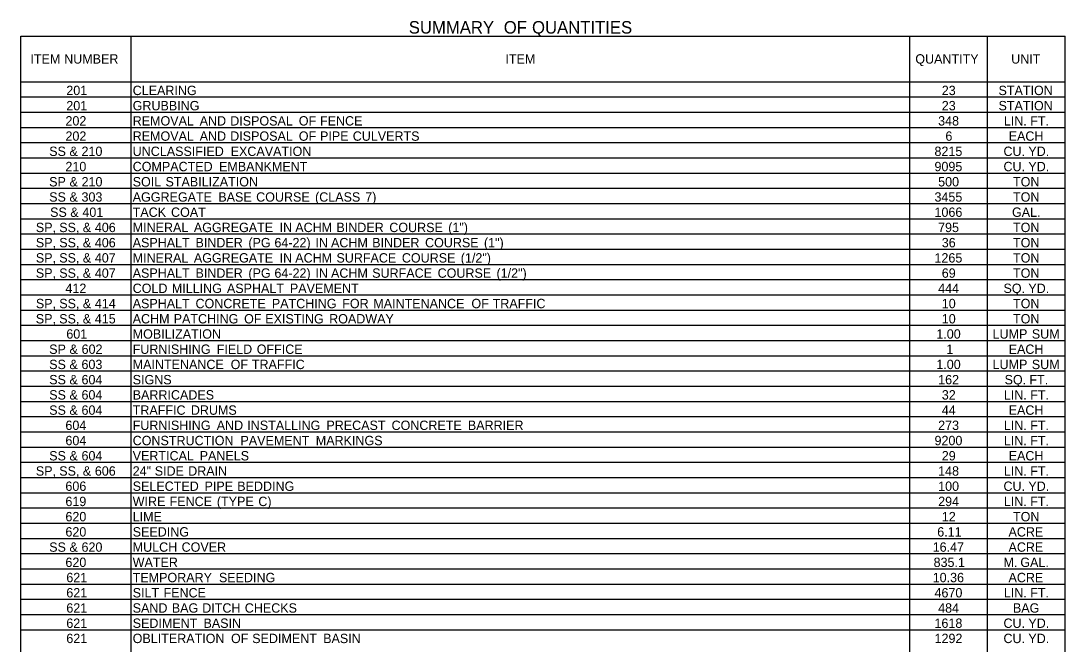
# Model space of a CAD drawing. Extents: x 1940653 to 1945779, y 534266 to 535271.
# Drawn here: x 1944649 to 1945251, y 534817 to 535176 of the extents above; entities that cross this region are included whole.
import ezdxf

# ---------------------------------------------------------------- set-up
doc = ezdxf.new("R2010")
doc.units = 0
doc.layers.add('Default', color=7, linetype='Continuous')

msp = doc.modelspace()

# ---------------------------------------------------------------- linework, layer by layer
at = {"layer": 'Default'}
for p, q in [((1944648.86, 535167.56), (1944712.48, 535167.56)), ((1944648.86, 535167.56), (1945251.26, 535167.56)), ((1944648.86, 534632.28), (1944648.86, 535167.56)), ((1944648.86, 534632.28), (1944648.86, 535167.56)), ((1944712.48, 534684.93), (1944712.48, 535167.56)), ((1945161.76, 534632.28), (1945161.76, 535167.56)), ((1945206.51, 534632.28), (1945206.51, 535167.56)), ((1945206.51, 534684.93), (1945206.51, 535167.56)), ((1945251.26, 534632.28), (1945251.26, 535167.56)), ((1944648.86, 535141.23), (1945251.26, 535141.23)), ((1944712.48, 534684.93), (1944712.48, 535141.23)), ((1945161.76, 534684.93), (1945161.76, 535141.23)), ((1944648.86, 535132.46), (1945251.26, 535132.46)), ((1944648.86, 535123.68), (1945251.26, 535123.68)), ((1944648.86, 535114.91), (1945251.26, 535114.91)), ((1944648.86, 535106.13), (1945251.26, 535106.13)), ((1944648.86, 535097.36), (1945251.26, 535097.36)), ((1944648.86, 535088.58), (1945251.26, 535088.58)), ((1944648.86, 535079.81), (1945251.26, 535079.81)), ((1944648.86, 535071.03), (1945251.26, 535071.03)), ((1944648.86, 535062.26), (1945251.26, 535062.26)), ((1944648.86, 535053.48), (1945251.26, 535053.48)), ((1944648.86, 535044.71), (1945251.26, 535044.71)), ((1944648.86, 535035.93), (1945251.26, 535035.93)), ((1944648.86, 535027.16), (1945251.26, 535027.16)), ((1944648.86, 535018.38), (1945251.26, 535018.38)), ((1944648.86, 535009.61), (1945251.26, 535009.61)), ((1944648.86, 535000.83), (1945251.26, 535000.83)), ((1944648.86, 534992.06), (1945251.26, 534992.06)), ((1944648.86, 534983.28), (1945251.26, 534983.28)), ((1944648.86, 534974.51), (1945251.26, 534974.51)), ((1944648.86, 534965.73), (1945251.26, 534965.73)), ((1944648.86, 534956.96), (1945251.26, 534956.96)), ((1944648.86, 534948.18), (1945251.26, 534948.18)), ((1944648.86, 534939.41), (1945251.26, 534939.41)), ((1944648.86, 534930.63), (1945251.26, 534930.63)), ((1944648.86, 534921.86), (1945251.26, 534921.86)), ((1944648.86, 534913.08), (1945251.26, 534913.08)), ((1944648.86, 534904.31), (1945251.26, 534904.31)), ((1944648.86, 534895.53), (1945251.26, 534895.53)), ((1944648.86, 534886.76), (1945251.26, 534886.76)), ((1944648.86, 534877.98), (1945251.26, 534877.98)), ((1944648.86, 534869.21), (1945251.26, 534869.21)), ((1944648.86, 534860.43), (1945251.26, 534860.43)), ((1944648.86, 534851.66), (1945251.26, 534851.66)), ((1944648.86, 534842.88), (1945251.26, 534842.88)), ((1944648.86, 534834.11), (1945251.26, 534834.11)), ((1944648.86, 534825.33), (1945251.26, 534825.33))]:
    msp.add_line(p, q, dxfattribs=at)

# ---------------------------------------------------------------- texts
for s, height, p in [(' SUMMARY', 7.2, (1944869.96, 535169)), (' OF', 7.2, (1944924.75, 535169)), (' QUANTITIES', 7.2, (1944941.05, 535169)), ('ITEM', 5.4, (1944654.34, 535151.7)), (' NUMBER', 5.4, (1944671.82, 535151.7)), ('ITEM', 5.4, (1944928.38, 535151.7)), ('QUANTITY', 5.4, (1945164.85, 535151.7)), ('UNIT', 5.4, (1945220.16, 535151.7)), ('201', 5.4, (1944675.07, 535133.54)), ('CLEARING', 5.4, (1944713.36, 535133.54)), ('23', 5.4, (1945180.11, 535133.54)), ('STATION', 5.4, (1945212.85, 535133.54)), ('201', 5.4, (1944675.07, 535124.76)), ('GRUBBING', 5.4, (1944713.36, 535124.76)), ('23', 5.4, (1945180.11, 535124.76)), ('STATION', 5.4, (1945212.85, 535124.76)), ('202', 5.4, (1944674.58, 535115.99)), ('REMOVAL', 5.4, (1944713.36, 535115.99)), (' AND', 5.4, (1944749.99, 535115.99)), (' DISPOSAL', 5.4, (1944767.61, 535115.99)), (' OF', 5.4, (1944807.18, 535115.99)), (' FENCE', 5.4, (1944819.41, 535115.99)), ('348', 5.4, (1945178.01, 535115.99)), ('LIN.', 5.4, (1945215.92, 535115.99)), (' FT.', 5.4, (1945229.1, 535115.99)), ('202', 5.4, (1944674.58, 535107.21)), ('REMOVAL', 5.4, (1944713.36, 535107.21)), (' AND', 5.4, (1944749.99, 535107.21)), (' DISPOSAL', 5.4, (1944767.61, 535107.21)), (' OF', 5.4, (1944807.18, 535107.21)), (' PIPE', 5.4, (1944819.41, 535107.21)), (' CULVERTS', 5.4, (1944838.3, 535107.21)), ('6', 5.4, (1945182.21, 535107.21)), ('EACH', 5.4, (1945218.71, 535107.21)), ('SS', 5.4, (1944665.2, 535098.44)), (' &', 5.4, (1944674.87, 535098.44)), (' 210', 5.4, (1944681.83, 535098.44)), ('UNCLASSIFIED', 5.4, (1944713.36, 535098.44)), (' EXCAVATION', 5.4, (1944767.88, 535098.44)), ('8215', 5.4, (1945175.9, 535098.44)), ('CU.', 5.4, (1945215.71, 535098.44)), (' YD.', 5.4, (1945228.05, 535098.44)), ('210', 5.4, (1944674.56, 535089.66)), ('COMPACTED', 5.4, (1944713.36, 535089.66)), (' EMBANKMENT', 5.4, (1944761.17, 535089.66)), ('9095', 5.4, (1945175.9, 535089.66)), ('CU.', 5.4, (1945215.71, 535089.66)), (' YD.', 5.4, (1945228.05, 535089.66)), ('SP', 5.4, (1944665.17, 535080.89)), (' &', 5.4, (1944674.9, 535080.89)), (' 210', 5.4, (1944681.86, 535080.89)), ('SOIL', 5.4, (1944713.36, 535080.89)), (' STABILIZATION', 5.4, (1944730.28, 535080.89)), ('500', 5.4, (1945178.03, 535080.89)), ('TON', 5.4, (1945221.23, 535080.89)), ('SS', 5.4, (1944665.19, 535072.11)), (' &', 5.4, (1944674.86, 535072.11)), (' 303', 5.4, (1944681.82, 535072.11)), ('AGGREGATE', 5.4, (1944713.36, 535072.11)), (' BASE', 5.4, (1944760.75, 535072.11)), (' COURSE', 5.4, (1944782.58, 535072.11)), (' (CLASS', 5.4, (1944816.56, 535072.11)), (' 7)', 5.4, (1944845.51, 535072.11)), ('3455', 5.4, (1945175.9, 535072.11)), ('TON', 5.4, (1945221.23, 535072.11)), ('SS', 5.4, (1944665.71, 535063.34)), (' &', 5.4, (1944675.38, 535063.34)), (' 401', 5.4, (1944682.34, 535063.34)), ('TACK', 5.4, (1944713.36, 535063.34)), (' COAT', 5.4, (1944733.47, 535063.34)), ('1066', 5.4, (1945175.92, 535063.34)), ('GAL.', 5.4, (1945220.62, 535063.34)), ('SP,', 5.4, (1944657.49, 535054.56)), (' SS,', 5.4, (1944668.98, 535054.56)), (' &', 5.4, (1944682.56, 535054.56)), (' 406', 5.4, (1944689.52, 535054.56)), ('MINERAL', 5.4, (1944713.36, 535054.56)), (' AGGREGATE', 5.4, (1944746.63, 535054.56)), (' IN', 5.4, (1944796.12, 535054.56)), (' ACHM', 5.4, (1944805.14, 535054.56)), (' BINDER', 5.4, (1944828.89, 535054.56)), (' COURSE', 5.4, (1944859.39, 535054.56)), (' (1")', 5.4, (1944893.37, 535054.56)), ('795', 5.4, (1945177.99, 535054.56)), ('TON', 5.4, (1945221.23, 535054.56)), ('SP,', 5.4, (1944657.49, 535045.79)), (' SS,', 5.4, (1944668.98, 535045.79)), (' &', 5.4, (1944682.56, 535045.79)), (' 406', 5.4, (1944689.52, 535045.79)), ('ASPHALT', 5.4, (1944713.36, 535045.79)), (' BINDER', 5.4, (1944747.59, 535045.79)), (' (PG', 5.4, (1944778.09, 535045.79)), (' 64-22)', 5.4, (1944793.13, 535045.79)), (' IN', 5.4, (1944816.75, 535045.79)), (' ACHM', 5.4, (1944825.77, 535045.79)), (' BINDER', 5.4, (1944849.52, 535045.79)), (' COURSE', 5.4, (1944880.02, 535045.79)), (' (1")', 5.4, (1944914, 535045.79)), ('36', 5.4, (1945180.11, 535045.79)), ('TON', 5.4, (1945221.23, 535045.79)), ('SP,', 5.4, (1944657.49, 535037.01)), (' SS,', 5.4, (1944668.98, 535037.01)), (' &', 5.4, (1944682.56, 535037.01)), (' 407', 5.4, (1944689.52, 535037.01)), ('MINERAL', 5.4, (1944713.36, 535037.01)), (' AGGREGATE', 5.4, (1944746.63, 535037.01)), (' IN', 5.4, (1944796.12, 535037.01)), (' ACHM', 5.4, (1944805.14, 535037.01)), (' SURFACE', 5.4, (1944828.89, 535037.01)), (' COURSE', 5.4, (1944866.64, 535037.01)), (' (1/2")', 5.4, (1944900.62, 535037.01)), ('1265', 5.4, (1945175.9, 535037.01)), ('TON', 5.4, (1945221.23, 535037.01)), ('SP,', 5.4, (1944657.49, 535028.24)), (' SS,', 5.4, (1944668.98, 535028.24)), (' &', 5.4, (1944682.56, 535028.24)), (' 407', 5.4, (1944689.52, 535028.24)), ('ASPHALT', 5.4, (1944713.36, 535028.24)), (' BINDER', 5.4, (1944747.59, 535028.24)), (' (PG', 5.4, (1944778.09, 535028.24)), (' 64-22)', 5.4, (1944793.13, 535028.24)), (' IN', 5.4, (1944816.75, 535028.24)), (' ACHM', 5.4, (1944825.77, 535028.24)), (' SURFACE', 5.4, (1944849.52, 535028.24)), (' COURSE', 5.4, (1944887.27, 535028.24)), (' (1/2")', 5.4, (1944921.24, 535028.24)), ('69', 5.4, (1945180.11, 535028.24)), ('TON', 5.4, (1945221.23, 535028.24)), ('412', 5.4, (1944674.58, 535019.46)), ('COLD', 5.4, (1944713.36, 535019.46)), (' MILLING', 5.4, (1944733.92, 535019.46)), (' ASPHALT', 5.4, (1944765.72, 535019.46)), ('SQ.', 5.4, (1945215.71, 535019.46)), (' PAVEMENT', 5.4, (1944802.05, 535019.46)), ('444', 5.4, (1945178.03, 535019.46)), (' YD.', 5.4, (1945228.05, 535019.46)), ('SP,', 5.4, (1944657.5, 535010.69)), (' SS,', 5.4, (1944668.99, 535010.69)), (' &', 5.4, (1944682.58, 535010.69)), (' 414', 5.4, (1944689.53, 535010.69)), ('ASPHALT', 5.4, (1944713.36, 535010.69)), (' CONCRETE', 5.4, (1944747.59, 535010.69)), (' PATCHING', 5.4, (1944791.63, 535010.69)), (' FOR', 5.4, (1944832.24, 535010.69)), (' MAINTENANCE', 5.4, (1944850.16, 535010.69)), (' OF', 5.4, (1944906.77, 535010.69)), (' TRAFFIC', 5.4, (1944919, 535010.69)), ('10', 5.4, (1945180.12, 535010.69)), ('TON', 5.4, (1945221.23, 535010.69)), ('SP,', 5.4, (1944657.46, 535001.91)), (' SS,', 5.4, (1944668.96, 535001.91)), (' &', 5.4, (1944682.54, 535001.91)), (' 415', 5.4, (1944689.5, 535001.91)), ('ACHM', 5.4, (1944713.36, 535001.91)), (' PATCHING', 5.4, (1944735.01, 535001.91)), (' OF', 5.4, (1944775.62, 535001.91)), (' EXISTING', 5.4, (1944787.85, 535001.91)), (' ROADWAY', 5.4, (1944824.69, 535001.91)), ('10', 5.4, (1945180.12, 535001.91)), ('TON', 5.4, (1945221.23, 535001.91)), ('601', 5.4, (1944675.07, 534993.14)), ('MOBILIZATION', 5.4, (1944713.36, 534993.14)), ('1.00', 5.4, (1945176.98, 534993.14)), ('LUMP', 5.4, (1945209.42, 534993.14)), (' SUM', 5.4, (1945230.06, 534993.14)), ('SP', 5.4, (1944665.18, 534984.36)), (' &', 5.4, (1944674.92, 534984.36)), (' 602', 5.4, (1944681.88, 534984.36)), ('FURNISHING', 5.4, (1944713.36, 534984.36)), (' FIELD', 5.4, (1944759.83, 534984.36)), (' OFFICE', 5.4, (1944782.91, 534984.36)), ('1', 5.4, (1945182.73, 534984.36)), ('EACH', 5.4, (1945218.71, 534984.36)), ('SS', 5.4, (1944665.19, 534975.59)), (' &', 5.4, (1944674.86, 534975.59)), (' 603', 5.4, (1944681.82, 534975.59)), ('MAINTENANCE', 5.4, (1944713.36, 534975.59)), (' OF', 5.4, (1944767.88, 534975.59)), (' TRAFFIC', 5.4, (1944780.1, 534975.59)), ('1.00', 5.4, (1945176.98, 534975.59)), ('LUMP', 5.4, (1945209.42, 534975.59)), (' SUM', 5.4, (1945230.06, 534975.59)), ('SS', 5.4, (1944665.2, 534966.81)), (' &', 5.4, (1944674.87, 534966.81)), (' 604', 5.4, (1944681.83, 534966.81)), ('SIGNS', 5.4, (1944713.36, 534966.81)), ('162', 5.4, (1945178.04, 534966.81)), ('SQ.', 5.4, (1945216.34, 534966.81)), (' FT.', 5.4, (1945228.68, 534966.81)), ('SS', 5.4, (1944665.2, 534958.04)), (' &', 5.4, (1944674.87, 534958.04)), (' 604', 5.4, (1944681.83, 534958.04)), ('BARRICADES', 5.4, (1944713.36, 534958.04)), ('32', 5.4, (1945180.14, 534958.04)), ('LIN.', 5.4, (1945215.92, 534958.04)), (' FT.', 5.4, (1945229.1, 534958.04)), ('SS', 5.4, (1944665.2, 534949.26)), (' &', 5.4, (1944674.87, 534949.26)), (' 604', 5.4, (1944681.83, 534949.26)), ('TRAFFIC', 5.4, (1944713.36, 534949.26)), (' DRUMS', 5.4, (1944744.91, 534949.26)), ('44', 5.4, (1945180.12, 534949.26)), ('EACH', 5.4, (1945218.71, 534949.26)), ('604', 5.4, (1944674.56, 534940.49)), ('FURNISHING', 5.4, (1944713.36, 534940.49)), (' AND', 5.4, (1944759.83, 534940.49)), (' INSTALLING', 5.4, (1944777.46, 534940.49)), (' PRECAST', 5.4, (1944823.1, 534940.49)), (' CONCRETE', 5.4, (1944860.69, 534940.49)), (' BARRIER', 5.4, (1944904.72, 534940.49)), ('273', 5.4, (1945178.02, 534940.49)), ('LIN.', 5.4, (1945215.92, 534940.49)), (' FT.', 5.4, (1945229.1, 534940.49)), ('604', 5.4, (1944674.56, 534931.71)), ('CONSTRUCTION', 5.4, (1944713.36, 534931.71)), (' PAVEMENT', 5.4, (1944773.52, 534931.71)), (' MARKINGS', 5.4, (1944816.98, 534931.71)), ('9200', 5.4, (1945175.93, 534931.71)), ('LIN.', 5.4, (1945215.92, 534931.71)), (' FT.', 5.4, (1945229.1, 534931.71)), ('SS', 5.4, (1944665.2, 534922.94)), (' &', 5.4, (1944674.87, 534922.94)), (' 604', 5.4, (1944681.83, 534922.94)), ('VERTICAL', 5.4, (1944713.36, 534922.94)), (' PANELS', 5.4, (1944749.99, 534922.94)), ('29', 5.4, (1945180.11, 534922.94)), ('EACH', 5.4, (1945218.71, 534922.94)), ('SP,', 5.4, (1944657.49, 534914.16)), (' SS,', 5.4, (1944668.98, 534914.16)), (' &', 5.4, (1944682.56, 534914.16)), (' 606', 5.4, (1944689.52, 534914.16)), ('24"', 5.4, (1944713.36, 534914.16)), (' SIDE', 5.4, (1944724.07, 534914.16)), (' DRAIN', 5.4, (1944743.37, 534914.16)), ('148', 5.4, (1945178.01, 534914.16)), ('LIN.', 5.4, (1945215.92, 534914.16)), (' FT.', 5.4, (1945229.1, 534914.16)), ('606', 5.4, (1944674.55, 534905.39)), ('SELECTED', 5.4, (1944713.36, 534905.39)), (' PIPE', 5.4, (1944752.79, 534905.39)), (' BEDDING', 5.4, (1944771.68, 534905.39)), ('100', 5.4, (1945178.03, 534905.39)), ('CU.', 5.4, (1945215.71, 534905.39)), (' YD.', 5.4, (1945228.05, 534905.39)), ('619', 5.4, (1944674.55, 534896.61)), ('WIRE', 5.4, (1944713.36, 534896.61)), (' FENCE', 5.4, (1944732.65, 534896.61)), (' (TYPE', 5.4, (1944759.92, 534896.61)), (' C)', 5.4, (1944783.83, 534896.61)), ('294', 5.4, (1945178.03, 534896.61)), ('LIN.', 5.4, (1945215.92, 534896.61)), (' FT.', 5.4, (1945229.1, 534896.61)), ('620', 5.4, (1944674.56, 534887.84)), ('LIME', 5.4, (1944713.36, 534887.84)), ('12', 5.4, (1945180.14, 534887.84)), ('TON', 5.4, (1945221.23, 534887.84)), ('620', 5.4, (1944674.56, 534879.06)), ('SEEDING', 5.4, (1944713.36, 534879.06)), ('6.11', 5.4, (1945177.49, 534879.06)), ('ACRE', 5.4, (1945218.61, 534879.06)), ('SS', 5.4, (1944665.2, 534870.29)), (' &', 5.4, (1944674.87, 534870.29)), (' 620', 5.4, (1944681.83, 534870.29)), ('MULCH', 5.4, (1944713.36, 534870.29)), (' COVER', 5.4, (1944739.57, 534870.29)), ('16.47', 5.4, (1945174.87, 534870.29)), ('ACRE', 5.4, (1945218.61, 534870.29)), ('620', 5.4, (1944674.56, 534861.51)), ('WATER', 5.4, (1944713.36, 534861.51)), ('835.1', 5.4, (1945175.39, 534861.51)), ('M.', 5.4, (1945215.71, 534861.51)), (' GAL.', 5.4, (1945223.43, 534861.51)), ('621', 5.4, (1944675.07, 534852.74)), ('TEMPORARY', 5.4, (1944713.36, 534852.74)), (' SEEDING', 5.4, (1944761.1, 534852.74)), ('10.36', 5.4, (1945174.87, 534852.74)), ('ACRE', 5.4, (1945218.61, 534852.74)), ('621', 5.4, (1944675.07, 534843.96)), ('SILT', 5.4, (1944713.36, 534843.96)), (' FENCE', 5.4, (1944729.14, 534843.96)), ('4670', 5.4, (1945175.93, 534843.96)), ('LIN.', 5.4, (1945215.92, 534843.96)), (' FT.', 5.4, (1945229.1, 534843.96)), ('621', 5.4, (1944675.07, 534835.19)), ('SAND', 5.4, (1944713.36, 534835.19)), (' BAG', 5.4, (1944733.92, 534835.19)), (' DITCH', 5.4, (1944751.48, 534835.19)), (' CHECKS', 5.4, (1944776.02, 534835.19)), ('484', 5.4, (1945178.03, 534835.19)), ('BAG', 5.4, (1945221.16, 534835.19)), ('621', 5.4, (1944675.07, 534826.41)), ('SEDIMENT', 5.4, (1944713.36, 534826.41)), (' BASIN', 5.4, (1944752.19, 534826.41)), ('1618', 5.4, (1945175.91, 534826.41)), ('CU.', 5.4, (1945215.71, 534826.41)), (' YD.', 5.4, (1945228.05, 534826.41)), ('621', 5.4, (1944675.07, 534817.64)), ('OBLITERATION', 5.4, (1944713.36, 534817.64)), (' OF', 5.4, (1944768.08, 534817.64)), (' SEDIMENT', 5.4, (1944780.31, 534817.64)), (' BASIN', 5.4, (1944821.24, 534817.64)), ('1292', 5.4, (1945175.95, 534817.64)), ('CU.', 5.4, (1945215.71, 534817.64)), (' YD.', 5.4, (1945228.05, 534817.64))]:
    msp.add_text(s, height=height, dxfattribs=at).set_placement(p)

doc.saveas('drawing.dxf')
